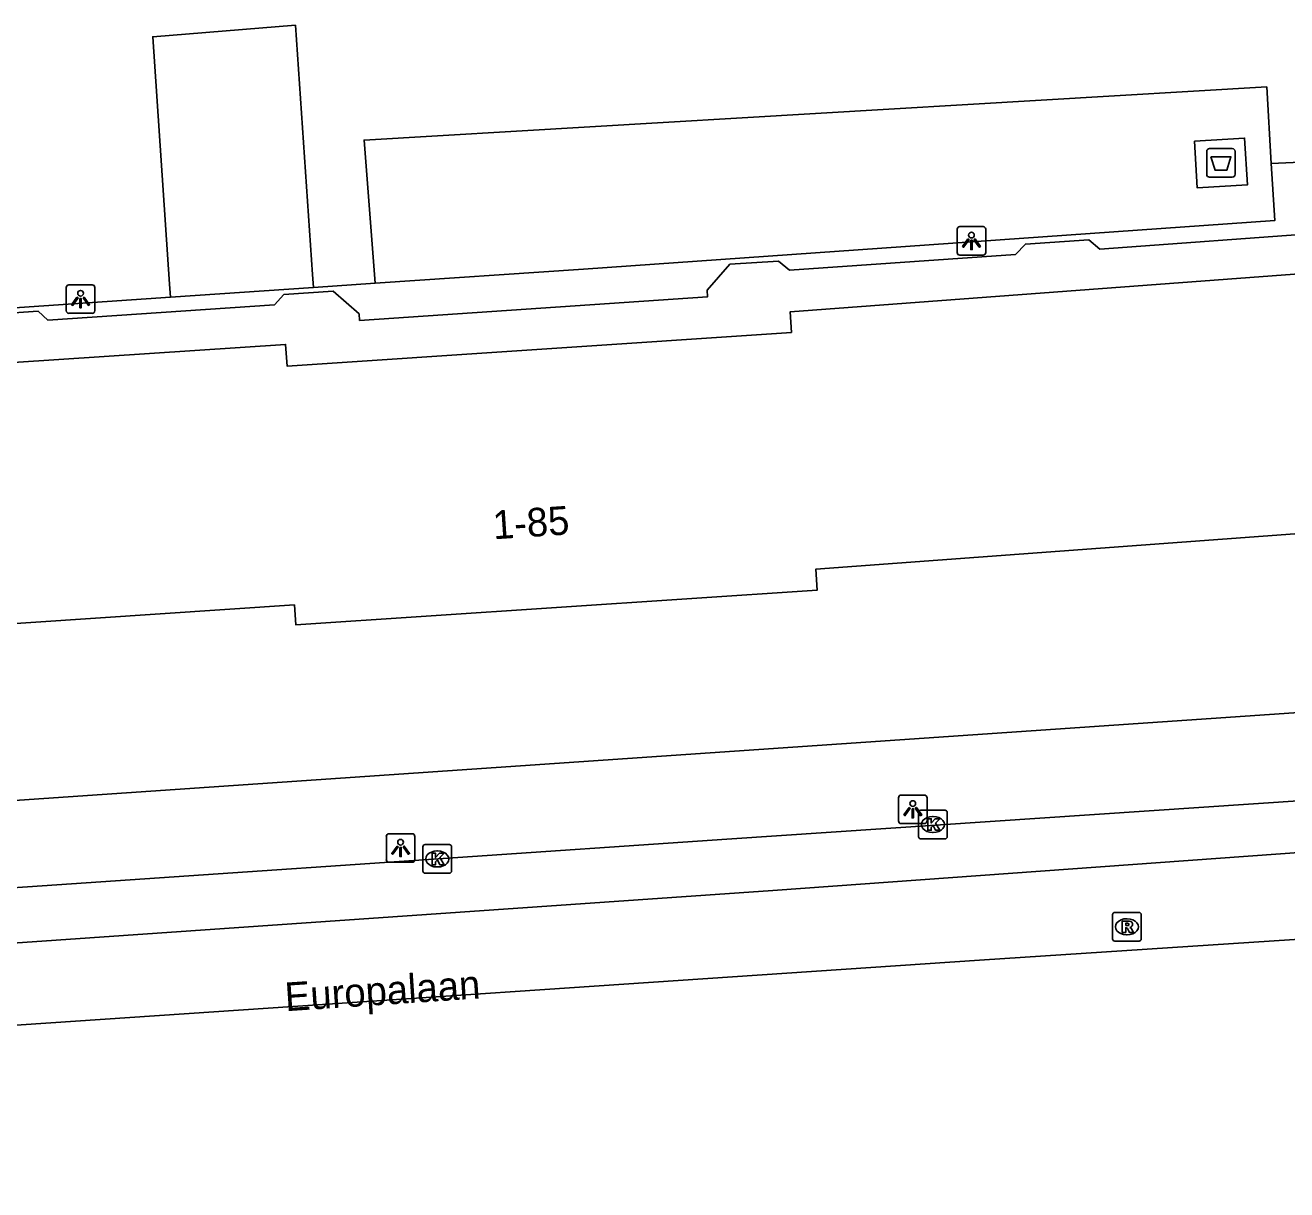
# Model space of a CAD drawing. Extents: x 161084 to 161928, y 385355 to 386522.
# Drawn here: x 161719.6 to 161763.67, y 385371.87 to 385412.57 of the extents above; entities that cross this region are included whole.
import ezdxf

# ---------------------------------------------------------------- set-up
doc = ezdxf.new("R2010")
doc.units = 0
for name, color, linetype in [('IMGEO_Afval_apart_plaats', 7, 'Continuous'), ('IMGEO_Kolk', 7, 'Continuous'), ('IMGEO_Lichtpunt', 7, 'Continuous'), ('IMGEO_Openbare_ruimte_label', 7, 'Continuous'), ('IMGEO_Pand', 7, 'Continuous'), ('IMGEO_Pand_nummerreeks', 7, 'Continuous'), ('IMGEO_Rijbaan_lokaal_gesloten', 7, 'Continuous'), ('IMGEO_Rijbaan_lokaal_open', 7, 'Continuous'), ('IMGEO_Rioolput', 7, 'Continuous'), ('IMGEO_Voetpad_gesloten', 7, 'Continuous'), ('IMGEO_Voetpad_open', 7, 'Continuous')]:
    doc.layers.add(name, color=color, linetype=linetype)

msp = doc.modelspace()

# ---------------------------------------------------------------- linework, layer by layer
at = {"layer": 'IMGEO_Afval_apart_plaats'}
for p, q in [((161760.879, 385407.356), (161760.879, 385408.156)), ((161760.879, 385408.156), (161760.879, 385407.356)), ((161760.979, 385408.256), (161761.769, 385408.256)), ((161761.769, 385408.256), (161760.979, 385408.256)), ((161761.869, 385408.156), (161761.869, 385407.356)), ((161761.869, 385407.356), (161761.869, 385408.156)), ((161761.769, 385407.256), (161760.979, 385407.256)), ((161760.979, 385407.256), (161761.769, 385407.256))]:
    msp.add_line(p, q, dxfattribs=at)
msp.add_lwpolyline([(161761.022, 385407.97), (161761.726, 385407.97), (161761.577, 385407.5), (161761.171, 385407.5), (161761.022, 385407.97)], dxfattribs=at)
for centre, start, end in [((161760.979, 385408.156), 90, 180), ((161760.979, 385408.156), 90, 180), ((161761.769, 385408.156), 0, 90), ((161761.769, 385408.156), 360, 90), ((161760.979, 385407.356), 180, 270), ((161760.979, 385407.356), 180, 270), ((161761.769, 385407.356), 270, 0), ((161761.769, 385407.356), 270, 0)]:
    msp.add_arc(centre, 0.1, start, end, dxfattribs=at)
at = {"layer": 'IMGEO_Kolk'}
for p, q in [((161750.886, 385385.135), (161751.738, 385385.135)), ((161750.811, 385384.209), (161750.811, 385385.061)), ((161751.299, 385384.915), (161751.324, 385384.915)), ((161751.812, 385385.061), (161751.812, 385384.209)), ((161751.322, 385384.355), (161751.297, 385384.355)), ((161733.494, 385383.006), (161733.494, 385383.858)), ((161733.569, 385383.932), (161734.421, 385383.932)), ((161734.495, 385383.858), (161734.495, 385383.006)), ((161751.738, 385384.135), (161750.886, 385384.135)), ((161733.982, 385383.712), (161734.007, 385383.712)), ((161734.421, 385382.932), (161733.569, 385382.932)), ((161734.005, 385383.152), (161733.98, 385383.152))]:
    msp.add_line(p, q, dxfattribs=at)
for points in [[(161750.886, 385385.135), (161751.738, 385385.135)], [(161750.811, 385384.209), (161750.811, 385385.061)], [(161751.132, 385384.835), (161751.255, 385384.835), (161751.255, 385384.684), (161751.385, 385384.835), (161751.549, 385384.835), (161751.403, 385384.684), (161751.556, 385384.435), (161751.404, 385384.435), (161751.319, 385384.599), (161751.255, 385384.532), (161751.255, 385384.435), (161751.132, 385384.435), (161751.132, 385384.835)], [(161751.812, 385385.061), (161751.812, 385384.209)], [(161733.494, 385383.006), (161733.494, 385383.858)], [(161733.569, 385383.932), (161734.421, 385383.932)], [(161734.495, 385383.858), (161734.495, 385383.006)], [(161751.738, 385384.135), (161750.886, 385384.135)], [(161733.815, 385383.632), (161733.938, 385383.632), (161733.938, 385383.481), (161734.068, 385383.632), (161734.232, 385383.632), (161734.086, 385383.481), (161734.239, 385383.232), (161734.087, 385383.232), (161734.002, 385383.396), (161733.938, 385383.329), (161733.938, 385383.232), (161733.815, 385383.232), (161733.815, 385383.632)], [(161734.421, 385382.932), (161733.569, 385382.932)]]:
    msp.add_lwpolyline(points, dxfattribs=at)
for centre, start, end in [((161750.888, 385385.059), 91.552, 178.448), ((161750.888, 385385.059), 91.552, 178.448), ((161751.736, 385385.059), 1.552, 88.448), ((161751.736, 385385.059), 1.552, 88.448), ((161733.571, 385383.856), 91.552, 178.448), ((161733.571, 385383.856), 91.552, 178.448), ((161734.419, 385383.856), 1.552, 88.448), ((161734.419, 385383.856), 1.552, 88.448), ((161750.888, 385384.211), 181.552, 268.448), ((161750.888, 385384.211), 181.552, 268.448), ((161751.736, 385384.211), 271.552, 358.448), ((161751.736, 385384.211), 271.552, 358.448), ((161733.571, 385383.008), 181.552, 268.448), ((161733.571, 385383.008), 181.552, 268.448), ((161734.419, 385383.008), 271.552, 358.448), ((161734.419, 385383.008), 271.552, 358.448)]:
    msp.add_arc(centre, 0.0765, start, end, dxfattribs=at)
for centre, major_axis, ratio, start_param, end_param in [((161751.298, 385384.635), (-0.387, 0.002), 0.722429, 4.712389, 7.853982), ((161751.323, 385384.635), (-0.39, 0.002), 0.717154, 1.570796, 4.712389), ((161733.981, 385383.432), (-0.387, 0.002), 0.722429, 4.712389, 7.853982), ((161734.006, 385383.432), (-0.39, 0.002), 0.717154, 1.570796, 4.712389)]:
    msp.add_ellipse(centre, major_axis=major_axis, ratio=ratio, start_param=start_param, end_param=end_param, dxfattribs=at)
at = {"layer": 'IMGEO_Lichtpunt'}
for p, q in [((161752.16, 385405.434), (161752.16, 385404.627)), ((161752.16, 385405.434), (161752.16, 385404.627)), ((161753.062, 385405.529), (161752.254, 385405.529)), ((161753.062, 385405.529), (161752.254, 385405.529)), ((161753.156, 385404.627), (161753.156, 385405.434)), ((161753.156, 385404.627), (161753.156, 385405.434)), ((161752.254, 385404.533), (161753.062, 385404.533)), ((161752.254, 385404.533), (161753.062, 385404.533)), ((161721.033, 385403.4), (161721.033, 385402.593)), ((161721.033, 385403.4), (161721.033, 385402.593)), ((161721.935, 385403.495), (161721.127, 385403.495)), ((161721.935, 385403.495), (161721.127, 385403.495)), ((161722.029, 385402.593), (161722.029, 385403.4)), ((161722.029, 385402.593), (161722.029, 385403.4)), ((161721.127, 385402.499), (161721.935, 385402.499)), ((161721.127, 385402.499), (161721.935, 385402.499)), ((161750.109, 385385.57), (161750.109, 385384.763)), ((161750.109, 385385.57), (161750.109, 385384.763)), ((161751.011, 385385.665), (161750.203, 385385.665)), ((161751.011, 385385.665), (161750.203, 385385.665)), ((161751.105, 385384.763), (161751.105, 385385.57)), ((161751.105, 385384.763), (161751.105, 385385.57)), ((161733.117, 385384.315), (161732.309, 385384.315)), ((161733.117, 385384.315), (161732.309, 385384.315)), ((161750.203, 385384.669), (161751.011, 385384.669)), ((161750.203, 385384.669), (161751.011, 385384.669)), ((161732.215, 385384.22), (161732.215, 385383.413)), ((161732.215, 385384.22), (161732.215, 385383.413)), ((161733.211, 385383.413), (161733.211, 385384.22)), ((161733.211, 385383.413), (161733.211, 385384.22)), ((161732.309, 385383.319), (161733.117, 385383.319)), ((161732.309, 385383.319), (161733.117, 385383.319))]:
    msp.add_line(p, q, dxfattribs=at)
for points in [[(161752.534, 385405.098), (161752.573, 385405.07), (161752.385, 385404.808), (161752.347, 385404.835), (161752.534, 385405.098)], [(161752.636, 385405.05), (161752.683, 385405.05), (161752.683, 385404.728), (161752.636, 385404.728), (161752.636, 385405.05)], [(161752.746, 385405.07), (161752.784, 385405.097), (161752.971, 385404.835), (161752.932, 385404.807), (161752.746, 385405.07)], [(161721.407, 385403.064), (161721.446, 385403.036), (161721.258, 385402.774), (161721.22, 385402.801), (161721.407, 385403.064)], [(161721.509, 385403.016), (161721.556, 385403.016), (161721.556, 385402.694), (161721.509, 385402.694), (161721.509, 385403.016)], [(161721.619, 385403.036), (161721.657, 385403.063), (161721.844, 385402.801), (161721.805, 385402.773), (161721.619, 385403.036)], [(161750.483, 385385.234), (161750.522, 385385.206), (161750.334, 385384.944), (161750.296, 385384.971), (161750.483, 385385.234)], [(161750.585, 385385.186), (161750.632, 385385.186), (161750.632, 385384.864), (161750.585, 385384.864), (161750.585, 385385.186)], [(161750.695, 385385.206), (161750.733, 385385.233), (161750.92, 385384.971), (161750.881, 385384.943), (161750.695, 385385.206)], [(161732.589, 385383.884), (161732.628, 385383.856), (161732.44, 385383.594), (161732.402, 385383.621), (161732.589, 385383.884)], [(161732.691, 385383.836), (161732.738, 385383.836), (161732.738, 385383.514), (161732.691, 385383.514), (161732.691, 385383.836)], [(161732.801, 385383.856), (161732.839, 385383.883), (161733.026, 385383.621), (161732.987, 385383.593), (161732.801, 385383.856)]]:
    msp.add_lwpolyline(points, dxfattribs=at)
for centre in [(161752.659, 385405.232), (161721.532, 385403.198), (161750.608, 385385.368), (161732.714, 385384.018)]:
    msp.add_circle(centre, 0.0994, dxfattribs=at)
for centre, start, end in [((161752.254, 385405.434), 90, 180), ((161752.254, 385405.434), 90, 180), ((161753.062, 385405.434), 0, 90), ((161753.062, 385405.434), 0, 90), ((161752.254, 385404.627), 180, 270), ((161752.254, 385404.627), 180, 270), ((161753.062, 385404.627), 270, 0), ((161753.062, 385404.627), 270, 360), ((161721.127, 385403.4), 90, 180), ((161721.127, 385403.4), 90, 180), ((161721.935, 385403.4), 0, 90), ((161721.935, 385403.4), 0, 90), ((161721.127, 385402.593), 180, 270), ((161721.127, 385402.593), 180, 270), ((161721.935, 385402.593), 270, 0), ((161721.935, 385402.593), 270, 360), ((161750.203, 385385.57), 90, 180), ((161750.203, 385385.57), 90, 180), ((161751.011, 385385.57), 0, 90), ((161751.011, 385385.57), 0, 90), ((161750.203, 385384.763), 180, 270), ((161750.203, 385384.763), 180, 270), ((161751.011, 385384.763), 270, 0), ((161751.011, 385384.763), 270, 360), ((161732.309, 385384.22), 90, 180), ((161732.309, 385384.22), 90, 180), ((161733.117, 385384.22), 0, 90), ((161733.117, 385384.22), 0, 90), ((161732.309, 385383.413), 180, 270), ((161732.309, 385383.413), 180, 270), ((161733.117, 385383.413), 270, 0), ((161733.117, 385383.413), 270, 360)]:
    msp.add_arc(centre, 0.0946, start, end, dxfattribs=at)
at = {"layer": 'IMGEO_Pand'}
for points in [[(161765.094, 385405.324), (161765.188, 385403.955), (161746.322, 385402.549), (161746.37, 385401.829), (161728.748, 385400.655), (161728.697, 385401.415), (161709.679, 385400.149), (161709.587, 385401.529)], [(161772.79, 385396.358), (161772.905, 385394.688), (161765.742, 385394.196), (161765.692, 385394.923), (161747.224, 385393.559), (161747.273, 385392.828), (161729.049, 385391.614), (161729.002, 385392.31), (161710.394, 385391.071), (161710.443, 385390.343), (161703.252, 385389.864), (161702.715, 385397.93)]]:
    msp.add_lwpolyline(points, dxfattribs=at)
at = {"layer": 'IMGEO_Rijbaan_lokaal_gesloten'}
for points in [[(161673.925, 385379.365), (161676.148, 385379.546), (161682.409, 385379.995), (161693.719, 385380.706), (161714.365, 385382.094), (161744.115, 385384.121), (161780.911, 385386.593), (161784.079, 385387.056), (161787.193, 385387.799), (161789.956, 385388.714)], [(161790.386, 385385.562), (161745.718, 385382.325), (161694.12, 385378.755), (161673.857, 385377.546), (161666.232, 385378.103)], [(161639.831, 385371.872), (161662.986, 385373.549), (161719.453, 385377.639), (161752.938, 385379.891), (161791.813, 385382.444)]]:
    msp.add_lwpolyline(points, dxfattribs=at)
at = {"layer": 'IMGEO_Rijbaan_lokaal_open'}
for points in [[(161724.677, 385403.063), (161724.641, 385403.52), (161724.055, 385412.163), (161729.039, 385412.566), (161729.63, 385403.859), (161729.67, 385403.402)], [(161731.827, 385403.548), (161731.435, 385408.554), (161762.977, 385410.409), (161763.135, 385407.73)], [(161763.135, 385407.73), (161764.16, 385407.778)], [(161729.67, 385403.402), (161731.827, 385403.548)], [(161718.019, 385402.612), (161724.677, 385403.063)]]:
    msp.add_lwpolyline(points, dxfattribs=at)
at = {"layer": 'IMGEO_Rioolput'}
for p, q in [((161757.589, 385380.638), (161757.589, 385381.49)), ((161757.664, 385381.564), (161758.516, 385381.564)), ((161758.077, 385381.344), (161758.102, 385381.344)), ((161758.59, 385381.49), (161758.59, 385380.638)), ((161758.1, 385380.784), (161758.075, 385380.784)), ((161758.516, 385380.564), (161757.664, 385380.564))]:
    msp.add_line(p, q, dxfattribs=at)
for points in [[(161757.589, 385380.638), (161757.589, 385381.49)], [(161757.664, 385381.564), (161758.516, 385381.564)], [(161758.178, 385381.262), (161757.926, 385381.264), (161757.926, 385380.864)], [(161758.104, 385381.183), (161758.05, 385381.183), (161758.05, 385381.102)], [(161758.59, 385381.49), (161758.59, 385380.638)], [(161757.926, 385380.864), (161758.05, 385380.864), (161758.05, 385381.026), (161758.061, 385381.026)], [(161758.05, 385381.102), (161758.102, 385381.102)], [(161758.108, 385380.997), (161758.179, 385380.864), (161758.319, 385380.864), (161758.254, 385380.99)], [(161758.516, 385380.564), (161757.664, 385380.564)]]:
    msp.add_lwpolyline(points, dxfattribs=at)
for centre, radius, start, end in [((161757.666, 385381.488), 0.0765, 91.552, 178.448), ((161757.666, 385381.488), 0.0765, 91.552, 178.448), ((161758.11, 385381.087), 0.0964, 77.0061, 93.1865), ((161758.124, 385381.144), 0.0378, 276.6634, 79.6772), ((161758.177, 385381.152), 0.109, 350.3612, 89.416), ((161758.514, 385381.488), 0.0765, 1.552, 88.448), ((161758.514, 385381.488), 0.0765, 1.552, 88.448), ((161758.06, 385380.973), 0.0533, 26.0293, 88.6989), ((161758.086, 385381.291), 0.19, 274.7715, 282.9687), ((161758.175, 385381.152), 0.112, 277.5842, 350.9817), ((161758.159, 385380.937), 0.108, 29.5134, 73.7905), ((161757.666, 385380.64), 0.0765, 181.552, 268.448), ((161757.666, 385380.64), 0.0765, 181.552, 268.448), ((161758.514, 385380.64), 0.0765, 271.552, 358.448), ((161758.514, 385380.64), 0.0765, 271.552, 358.448)]:
    msp.add_arc(centre, radius, start, end, dxfattribs=at)
for centre, major_axis, ratio, start_param, end_param in [((161758.076, 385381.064), (-0.387, 0.002), 0.722429, 4.712389, 7.853982), ((161758.101, 385381.064), (-0.39, 0.002), 0.717154, 1.570796, 4.712389)]:
    msp.add_ellipse(centre, major_axis=major_axis, ratio=ratio, start_param=start_param, end_param=end_param, dxfattribs=at)
at = {"layer": 'IMGEO_Voetpad_gesloten'}
msp.add_lwpolyline([(161760.446, 385408.514), (161762.2, 385408.622), (161762.301, 385406.987), (161760.547, 385406.879), (161760.446, 385408.514)], dxfattribs=at)
at = {"layer": 'IMGEO_Voetpad_open'}
for points in [[(161731.827, 385403.548), (161739.107, 385404.042), (161763.252, 385405.741), (161763.135, 385407.73)], [(161709.587, 385401.529), (161717.519, 385402.066), (161717.836, 385402.418), (161720.047, 385402.571), (161720.394, 385402.261), (161728.312, 385402.797), (161728.638, 385403.152), (161730.352, 385403.268), (161731.266, 385402.48), (161731.282, 385402.252), (161743.433, 385403.074), (161743.429, 385403.311), (161744.219, 385404.211), (161745.914, 385404.324), (161746.297, 385404.011), (161754.193, 385404.551), (161754.546, 385404.918), (161756.76, 385405.066), (161757.139, 385404.742), (161765.094, 385405.324)], [(161724.677, 385403.063), (161729.67, 385403.402)], [(161699.842, 385384.149), (161775.141, 385389.302)]]:
    msp.add_lwpolyline(points, dxfattribs=at)

# ---------------------------------------------------------------- texts
at = {"layer": 'IMGEO_Openbare_ruimte_label'}
msp.add_text('Europalaan', height=1, rotation=3.7836, dxfattribs=at).set_placement((161728.699, 385378.11))
at = {"layer": 'IMGEO_Pand_nummerreeks'}
msp.add_text('1-85', height=1, rotation=3.8112, dxfattribs=at).set_placement((161735.965, 385394.6))

doc.saveas('drawing.dxf')
